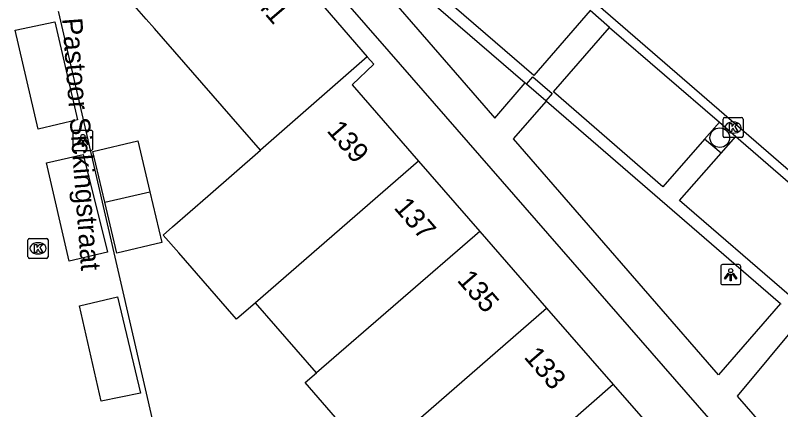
# Model space of a CAD drawing. Extents: x 161882 to 162509, y 381687 to 382379.
# Drawn here: x 161978.02 to 162016.16, y 382160.76 to 382180.43 of the extents above; entities that cross this region are included whole.
import ezdxf

# ---------------------------------------------------------------- set-up
doc = ezdxf.new("R2010")
doc.units = 0
for name, color, linetype in [('IMGEO_Boom', 7, 'Continuous'), ('IMGEO_Kolk', 7, 'Continuous'), ('IMGEO_Lichtpunt', 7, 'Continuous'), ('IMGEO_Openbare_ruimte_label', 7, 'Continuous'), ('IMGEO_Pand', 7, 'Continuous'), ('IMGEO_Pand_nummerreeks', 7, 'Continuous'), ('IMGEO_Parkeervlak_open', 7, 'Continuous'), ('IMGEO_Rijbaan_lokaal_open', 7, 'Continuous'), ('IMGEO_Voetpad_open', 7, 'Continuous')]:
    doc.layers.add(name, color=color, linetype=linetype)

msp = doc.modelspace()

# ---------------------------------------------------------------- linework, layer by layer
at = {"layer": 'IMGEO_Boom'}
msp.add_circle((162013.128, 382174.328), 0.489, dxfattribs=at)
at = {"layer": 'IMGEO_Kolk'}
for p, q in [((162013.289, 382174.406), (162013.289, 382175.258)), ((162013.364, 382175.332), (162014.216, 382175.332)), ((162014.29, 382175.258), (162014.29, 382174.406)), ((162013.777, 382175.112), (162013.802, 382175.112)), ((162013.8, 382174.552), (162013.775, 382174.552)), ((162014.216, 382174.332), (162013.364, 382174.332)), ((161978.654, 382168.381), (161978.654, 382169.233)), ((161978.729, 382169.307), (161979.581, 382169.307)), ((161979.142, 382169.087), (161979.167, 382169.087)), ((161979.655, 382169.233), (161979.655, 382168.381)), ((161979.581, 382168.307), (161978.729, 382168.307)), ((161979.165, 382168.527), (161979.14, 382168.527))]:
    msp.add_line(p, q, dxfattribs=at)
for points in [[(162013.289, 382174.406), (162013.289, 382175.258)], [(162013.364, 382175.332), (162014.216, 382175.332)], [(162014.29, 382175.258), (162014.29, 382174.406)], [(162013.61, 382175.032), (162013.733, 382175.032), (162013.733, 382174.881), (162013.863, 382175.032), (162014.027, 382175.032), (162013.881, 382174.881), (162014.034, 382174.632), (162013.882, 382174.632), (162013.797, 382174.796), (162013.733, 382174.729), (162013.733, 382174.632), (162013.61, 382174.632), (162013.61, 382175.032)], [(162014.216, 382174.332), (162013.364, 382174.332)], [(161978.654, 382168.381), (161978.654, 382169.233)], [(161978.729, 382169.307), (161979.581, 382169.307)], [(161979.655, 382169.233), (161979.655, 382168.381)], [(161978.975, 382169.007), (161979.098, 382169.007), (161979.098, 382168.856), (161979.228, 382169.007), (161979.392, 382169.007), (161979.246, 382168.856), (161979.399, 382168.607), (161979.247, 382168.607), (161979.162, 382168.771), (161979.098, 382168.704), (161979.098, 382168.607), (161978.975, 382168.607), (161978.975, 382169.007)], [(161979.581, 382168.307), (161978.729, 382168.307)]]:
    msp.add_lwpolyline(points, dxfattribs=at)
for centre, start, end in [((162013.366, 382175.256), 91.552, 178.448), ((162013.366, 382175.256), 91.552, 178.448), ((162014.214, 382175.256), 1.552, 88.448), ((162014.214, 382175.256), 1.552, 88.448), ((162013.366, 382174.408), 181.552, 268.448), ((162013.366, 382174.408), 181.552, 268.448), ((162014.214, 382174.408), 271.552, 358.448), ((162014.214, 382174.408), 271.552, 358.448), ((161978.731, 382169.231), 91.552, 178.448), ((161978.731, 382169.231), 91.552, 178.448), ((161979.579, 382169.231), 1.552, 88.448), ((161979.579, 382169.231), 1.552, 88.448), ((161978.731, 382168.383), 181.552, 268.448), ((161978.731, 382168.383), 181.552, 268.448), ((161979.579, 382168.383), 271.552, 358.448), ((161979.579, 382168.383), 271.552, 358.448)]:
    msp.add_arc(centre, 0.0765, start, end, dxfattribs=at)
for centre, major_axis, ratio, start_param, end_param in [((162013.776, 382174.832), (-0.387, 0.002), 0.722429, 4.712389, 7.853982), ((162013.801, 382174.832), (-0.39, 0.002), 0.717154, 1.570796, 4.712389), ((161979.141, 382168.807), (-0.387, 0.002), 0.722429, 4.712389, 7.853982), ((161979.166, 382168.807), (-0.39, 0.002), 0.717154, 1.570796, 4.712389)]:
    msp.add_ellipse(centre, major_axis=major_axis, ratio=ratio, start_param=start_param, end_param=end_param, dxfattribs=at)
at = {"layer": 'IMGEO_Lichtpunt'}
for p, q in [((161980.889, 382174.595), (161980.889, 382173.788)), ((161980.889, 382174.595), (161980.889, 382173.788)), ((161981.791, 382174.69), (161980.983, 382174.69)), ((161981.791, 382174.69), (161980.983, 382174.69)), ((161981.885, 382173.788), (161981.885, 382174.595)), ((161981.885, 382173.788), (161981.885, 382174.595)), ((161980.983, 382173.694), (161981.791, 382173.694)), ((161980.983, 382173.694), (161981.791, 382173.694)), ((162014.077, 382167.996), (162013.269, 382167.996)), ((162014.077, 382167.996), (162013.269, 382167.996)), ((162013.175, 382167.901), (162013.175, 382167.094)), ((162013.175, 382167.901), (162013.175, 382167.094)), ((162014.171, 382167.094), (162014.171, 382167.901)), ((162014.171, 382167.094), (162014.171, 382167.901)), ((162013.269, 382167), (162014.077, 382167)), ((162013.269, 382167), (162014.077, 382167))]:
    msp.add_line(p, q, dxfattribs=at)
for points in [[(161981.263, 382174.259), (161981.302, 382174.231), (161981.114, 382173.969), (161981.076, 382173.996), (161981.263, 382174.259)], [(161981.365, 382174.211), (161981.412, 382174.211), (161981.412, 382173.889), (161981.365, 382173.889), (161981.365, 382174.211)], [(161981.475, 382174.231), (161981.513, 382174.258), (161981.7, 382173.996), (161981.661, 382173.968), (161981.475, 382174.231)], [(162013.549, 382167.565), (162013.588, 382167.537), (162013.4, 382167.275), (162013.362, 382167.302), (162013.549, 382167.565)], [(162013.761, 382167.537), (162013.799, 382167.564), (162013.986, 382167.302), (162013.947, 382167.274), (162013.761, 382167.537)], [(162013.651, 382167.517), (162013.698, 382167.517), (162013.698, 382167.195), (162013.651, 382167.195), (162013.651, 382167.517)]]:
    msp.add_lwpolyline(points, dxfattribs=at)
for centre in [(161981.388, 382174.393), (162013.674, 382167.699)]:
    msp.add_circle(centre, 0.0994, dxfattribs=at)
for centre, start, end in [((161980.983, 382174.595), 90, 180), ((161980.983, 382174.595), 90, 180), ((161981.791, 382174.595), 0, 90), ((161981.791, 382174.595), 0, 90), ((161980.983, 382173.788), 180, 270), ((161980.983, 382173.788), 180, 270), ((161981.791, 382173.788), 270, 0), ((161981.791, 382173.788), 270, 360), ((162013.269, 382167.901), 90, 180), ((162013.269, 382167.901), 90, 180), ((162014.077, 382167.901), 0, 90), ((162014.077, 382167.901), 0, 90), ((162013.269, 382167.094), 180, 270), ((162013.269, 382167.094), 180, 270), ((162014.077, 382167.094), 270, 0), ((162014.077, 382167.094), 270, 360)]:
    msp.add_arc(centre, 0.0946, start, end, dxfattribs=at)
at = {"layer": 'IMGEO_Pand'}
for points in [[(161990.236, 382173.705), (161984.955, 382179.772), (161984.547, 382180.24), (161983.97, 382180.903), (161984.553, 382181.411), (161988.906, 382185.2), (161989.336, 382185.574), (161995.56, 382178.365)], [(161995.56, 382178.365), (161990.236, 382173.705)], [(161995.56, 382178.365), (161995.886, 382177.987), (161994.815, 382176.958), (161998.118, 382173.163)], [(161982.483, 382171.107), (161981.885, 382173.642), (161984.124, 382174.17), (161984.722, 382171.635)], [(161989.985, 382166.096), (161989.039, 382165.274), (161988.921, 382165.41), (161986.163, 382168.584), (161985.395, 382169.468), (161985.858, 382169.874), (161987.617, 382171.413), (161990.236, 382173.705)], [(161998.118, 382173.163), (161989.985, 382166.096)], [(161998.118, 382173.163), (162001.169, 382169.656)], [(161984.722, 382171.635), (161985.32, 382169.1), (161983.081, 382168.572), (161982.483, 382171.107)], [(161982.483, 382171.107), (161984.722, 382171.635)], [(162001.169, 382169.656), (161993.025, 382162.6)], [(162001.169, 382169.656), (162004.5, 382165.829)], [(161993.025, 382162.6), (161989.985, 382166.096)], [(161995.812, 382158.259), (162004.5, 382165.829)], [(162004.5, 382165.829), (162007.819, 382162.014)], [(161995.812, 382158.259), (161992.464, 382162.114), (161993.025, 382162.6)], [(162007.819, 382162.014), (161998.778, 382154.082)], [(162007.819, 382162.014), (162011.263, 382158.057)]]:
    msp.add_lwpolyline(points, dxfattribs=at)
at = {"layer": 'IMGEO_Parkeervlak_open'}
for points in [[(162013.107, 382175.099), (162012.366, 382174.25)], [(162013.2, 382173.552), (162013.934, 382174.385)]]:
    msp.add_lwpolyline(points, dxfattribs=at)
at = {"layer": 'IMGEO_Rijbaan_lokaal_open'}
for points in [[(162036.646, 382154.691), (162036.967, 382155.028), (162001.899, 382185.403), (162000.705, 382186.422), (162000.438, 382186.65), (162000.135, 382186.301)], [(162010.46, 382123.082), (161990.302, 382150.73), (161984.998, 382159.715), (161980.188, 382180.574), (161980.177, 382180.625)], [(162007.638, 382179.817), (162006.67, 382180.667)], [(161979.163, 382174.76), (161978.022, 382179.691), (161979.995, 382180.105), (161981.127, 382175.215), (161979.163, 382174.76)], [(162007.638, 382179.817), (162013.107, 382175.099)], [(162013.107, 382175.099), (162013.934, 382174.385)], [(162013.934, 382174.385), (162019.379, 382169.666)], [(161980.7, 382168.171), (161979.571, 382173.07), (161981.406, 382173.489), (161982.619, 382168.615), (161980.7, 382168.171)], [(161982.307, 382161.182), (161981.218, 382165.944), (161983.116, 382166.391), (161984.258, 382161.587), (161982.307, 382161.182)]]:
    msp.add_lwpolyline(points, dxfattribs=at)
at = {"layer": 'IMGEO_Voetpad_open'}
for points in [[(162028.288, 382138.462), (162030.201, 382140.112), (161996.66, 382178.627), (161990.016, 382186.254)], [(161993.312, 382185.812), (161993.031, 382185.565), (162001.926, 382175.294), (162003.438, 382177.057)], [(161993.312, 382185.812), (161997.32, 382182.356), (162003.438, 382177.057)], [(162006.67, 382180.667), (162003.868, 382177.436), (161998.439, 382182.114), (162000.513, 382184.511)], [(162012.366, 382174.25), (162010.291, 382171.872), (162004.846, 382176.622), (162007.638, 382179.817)], [(162003.503, 382177.001), (162003.81, 382177.37), (162004.774, 382176.539), (162004.468, 382176.171)], [(162003.438, 382177.057), (162003.503, 382177.001)], [(162004.468, 382176.171), (162003.503, 382177.001)], [(162016.152, 382166.051), (162013.07, 382162.502), (162002.856, 382174.263), (162004.491, 382176.151)], [(162004.468, 382176.171), (162004.491, 382176.151)], [(162004.491, 382176.151), (162016.152, 382166.051)], [(162013.2, 382173.552), (162012.366, 382174.25)], [(162019.379, 382169.666), (162016.581, 382166.476), (162011.116, 382171.188), (162013.2, 382173.552)], [(162016.152, 382166.051), (162016.175, 382166.031)], [(162028.853, 382155.032), (162024.17, 382149.745), (162014.005, 382161.432), (162017.138, 382165.198)]]:
    msp.add_lwpolyline(points, dxfattribs=at)

# ---------------------------------------------------------------- texts
at = {"layer": 'IMGEO_Openbare_ruimte_label'}
msp.add_text('Pastoor Sickingstraat', height=1, rotation=274.302, dxfattribs=at).set_placement((161980.357, 382180.273))
at = {"layer": 'IMGEO_Pand_nummerreeks'}
for s, rotation, p in [('141', 310.6053, (161989.462, 382181.611)), ('139', 310.8345, (161993.506, 382174.661)), ('137', 310.8345, (161996.848, 382170.821)), ('135', 310.8345, (161999.997, 382167.202)), ('133', 310.8345, (162003.329, 382163.372))]:
    msp.add_text(s, height=1, rotation=rotation, dxfattribs=at).set_placement(p)

doc.saveas('drawing.dxf')
